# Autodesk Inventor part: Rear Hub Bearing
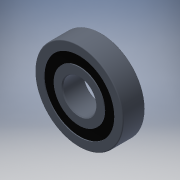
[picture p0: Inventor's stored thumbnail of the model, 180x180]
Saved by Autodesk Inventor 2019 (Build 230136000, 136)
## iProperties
Shininess: 50.0
Compacted: True
Length Units: 11272
Angle Units: 11279
Time Units: 11290
Mass Units: 11286
Length Display Precision: 4
Angle Display Precision: 2
Company: Autodesk
Created: 2000-05
Part Number: Rear Hub Bearing
Project: Inventor Samples
User Status: IN PROGRESS
Document SubType Name: Modeling
Designer: Autodesk, Inc.
Density: 8.08 g/cm^3
Material: Stainless Steel
Mass: 2.70813 g
Surface Area: 3.99293 cm^2
Volume: 0.335165 cm^3
Appearance: Dark Grey
Density: 0.0
Volumn: 0.0
Area: 0.0
PropertySet Name: Model Information
Control State: 0
Master: False
Checked Out: False
Checked Out Date: 2018-05-30
Last Check In Date: 2018-05-30
Author: Autodesk, Inc.
Revision Number: A
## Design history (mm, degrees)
node "Extrusion1" dims "d5" = 3.175, "d6" = 0
  sketch "Sketch2"
    geometry: C1 r 2.381 at (10.478, 10.795); C2 r 6.35 at (10.478, 10.795); C3 r 5.08 at (10.478, 10.795); C4 r 3.651 at (10.478, 10.795)
    constraints: 4 centre point, 2 coincident, 1 concentric, 1 other
    dimensions: "d1" = 12.7 diameter of C2; "d2" = 1.27 radial gap between concentric circles of C2 C3; "d4" = 1.27 radial gap between concentric circles of C1 C4; "d15" = 4.7625 diameter of C1
workplane "Work Plane1"
node "Fillet1" dims "d12" = 0.127
node "Chamfer1" dims "d13" = 0.127, "d14" = 0.127, "d18" = 45 deg
node "Extrusion2" dims "d16" = 2.921 (computed from d5), "d17" = 0
  sketch "Sketch4"
    geometry: C1 r 5.08 at (0, 0) reference; C2 r 3.651 at (0, 0) reference
body "Solid1"
other parameters: "d7" = -1.5875 (= -0.5 x d5)
